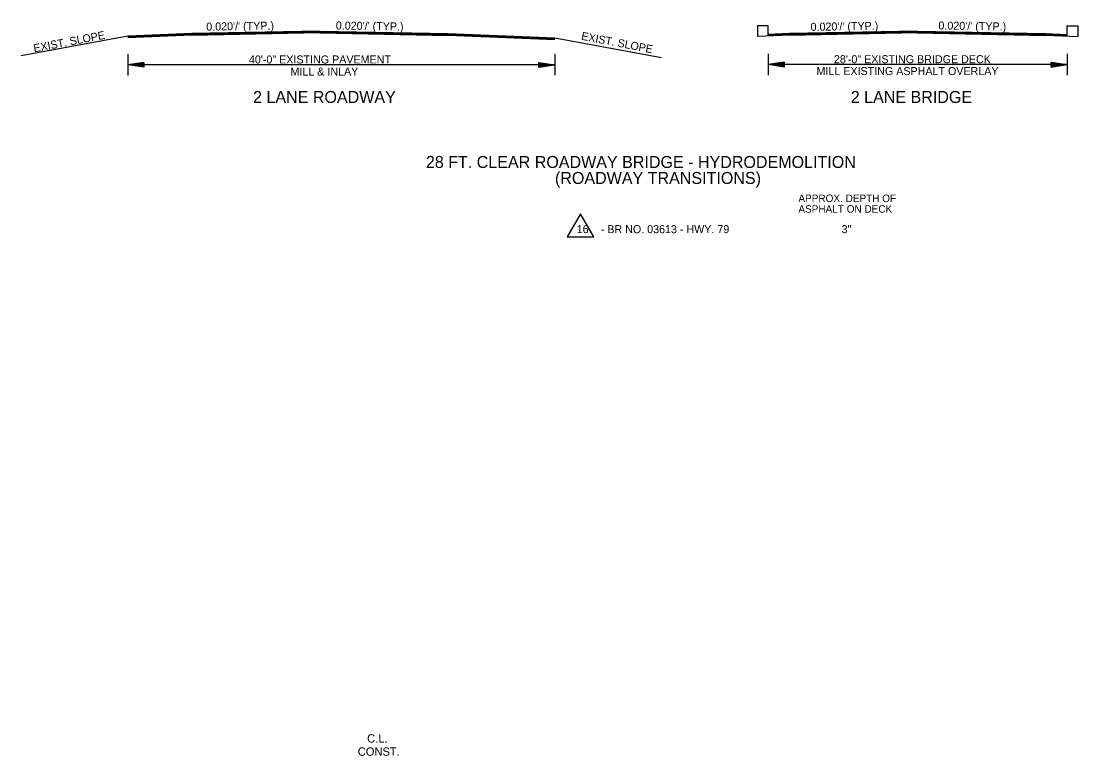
# Model space of a CAD drawing. Extents: x 549600 to 1930787, y -1955432 to 596640.
# Drawn here: x 551022 to 552012, y -1953335 to -1952647 of the extents above; entities that cross this region are included whole.
import ezdxf

# ---------------------------------------------------------------- set-up
doc = ezdxf.new("R2010")
doc.units = 0
for name, color, linetype in [('R_Border', 7, 'Continuous'), ('R_Border Notes', 7, 'Continuous'), ('S_AREA_CALC', 7, 'Continuous')]:
    doc.layers.add(name, color=color, linetype=linetype)

msp = doc.modelspace()

# ---------------------------------------------------------------- linework, layer by layer
at = {"layer": 'R_Border'}
for p, q in [((551711.85, -1952651.18), (551711.85, -1952661.29)), ((551722.02, -1952651.18), (551711.85, -1952651.18)), ((551722.02, -1952660.59), (551722.02, -1952651.18)), ((552002.02, -1952660.59), (552002.02, -1952651.18)), ((552002.02, -1952651.18), (552012.18, -1952651.18)), ((552012.18, -1952651.18), (552012.18, -1952661.29)), ((551533.72, -1952848.95), (551558.52, -1952848.95))]:
    msp.add_line(p, q, dxfattribs=at)
msp.add_lwpolyline([(551558.52, -1952848.95), (551546.12, -1952827.47), (551533.72, -1952848.95)], dxfattribs=at)
at = {"layer": 'S_AREA_CALC'}
for p, q in [((551122.02, -1952660.99), (551021.95, -1952679.36)), ((551182.02, -1952658.59), (551122.02, -1952660.99)), ((551182.02, -1952658.89), (551122.02, -1952661.29)), ((551182.02, -1952659.19), (551122.02, -1952661.59)), ((551182.02, -1952659.49), (551122.02, -1952661.89)), ((551182.02, -1952659.79), (551122.02, -1952662.19)), ((551182.02, -1952660.09), (551122.02, -1952662.49)), ((551302.02, -1952656.19), (551182.02, -1952658.59)), ((551302.02, -1952656.49), (551182.02, -1952658.89)), ((551302.02, -1952656.79), (551182.02, -1952659.19)), ((551302.02, -1952657.09), (551182.02, -1952659.49)), ((551302.02, -1952657.39), (551182.02, -1952659.79)), ((551302.02, -1952657.69), (551182.02, -1952660.09)), ((551302.02, -1952657.86), (551182.02, -1952660.26)), ((551302.02, -1952656.19), (551422.02, -1952658.59)), ((551302.02, -1952656.49), (551422.02, -1952658.89)), ((551302.02, -1952656.79), (551422.02, -1952659.19)), ((551302.02, -1952657.09), (551422.02, -1952659.49)), ((551302.02, -1952657.39), (551422.02, -1952659.79)), ((551302.02, -1952657.69), (551422.02, -1952660.09)), ((551302.02, -1952657.86), (551422.02, -1952660.26)), ((551422.02, -1952658.59), (551522.02, -1952662.59)), ((551422.02, -1952658.89), (551522.02, -1952662.89)), ((551422.02, -1952659.19), (551522.02, -1952663.19)), ((551422.02, -1952659.49), (551522.02, -1952663.49)), ((551422.02, -1952659.79), (551522.02, -1952663.79)), ((551422.02, -1952660.09), (551522.02, -1952664.09)), ((551522.02, -1952662.59), (551622.09, -1952680.96)), ((551742.02, -1952660.09), (551711.85, -1952661.29)), ((551742.02, -1952658.59), (551722.02, -1952659.39)), ((551742.02, -1952658.89), (551722.02, -1952659.69)), ((551742.02, -1952659.19), (551722.02, -1952659.99)), ((551742.02, -1952659.49), (551722.02, -1952660.29)), ((551742.02, -1952659.79), (551722.02, -1952660.59)), ((551862.02, -1952656.19), (551742.02, -1952658.59)), ((551862.02, -1952656.49), (551742.02, -1952658.89)), ((551862.02, -1952656.79), (551742.02, -1952659.19)), ((551862.02, -1952657.09), (551742.02, -1952659.49)), ((551862.02, -1952657.39), (551742.02, -1952659.79)), ((551862.02, -1952657.69), (551742.02, -1952660.09)), ((551862.02, -1952657.86), (551742.02, -1952660.26)), ((551862.02, -1952656.19), (551982.02, -1952658.59)), ((551862.02, -1952656.49), (551982.02, -1952658.89)), ((551862.02, -1952656.79), (551982.02, -1952659.19)), ((551862.02, -1952657.09), (551982.02, -1952659.49)), ((551862.02, -1952657.39), (551982.02, -1952659.79)), ((551862.02, -1952657.69), (551982.02, -1952660.09)), ((551862.02, -1952657.86), (551982.02, -1952660.26)), ((551982.02, -1952658.59), (552002.02, -1952659.39)), ((551982.02, -1952658.89), (552002.02, -1952659.69)), ((551982.02, -1952659.19), (552002.02, -1952659.99)), ((551982.02, -1952659.49), (552002.02, -1952660.29)), ((551982.02, -1952659.79), (552002.02, -1952660.59)), ((551982.02, -1952660.09), (552012.18, -1952661.29)), ((551122.02, -1952677.84), (551122.02, -1952697.84)), ((551522.02, -1952677.59), (551522.02, -1952697.59)), ((551722.02, -1952677.59), (551722.02, -1952697.59)), ((552002.02, -1952677.35), (552002.02, -1952697.35)), ((551137.02, -1952685.59), (551122.02, -1952687.84)), ((551137.02, -1952690.09), (551122.02, -1952687.84)), ((551522.02, -1952687.84), (551122.02, -1952687.84)), ((551137.02, -1952685.97), (551124.52, -1952687.84)), ((551137.02, -1952689.72), (551124.52, -1952687.84)), ((551137.02, -1952686.35), (551127.1, -1952687.84)), ((551137.02, -1952689.34), (551127.1, -1952687.84)), ((551137.02, -1952686.73), (551129.6, -1952687.84)), ((551137.02, -1952688.96), (551129.6, -1952687.84)), ((551137.02, -1952687.12), (551132.14, -1952687.84)), ((551137.02, -1952688.58), (551132.14, -1952687.84)), ((551137.02, -1952687.49), (551134.65, -1952687.84)), ((551137.02, -1952688.2), (551134.65, -1952687.84)), ((551137.02, -1952685.59), (551137.02, -1952690.09)), ((551507.02, -1952685.59), (551522.02, -1952687.84)), ((551507.02, -1952690.09), (551507.02, -1952685.59)), ((551507.02, -1952685.97), (551519.51, -1952687.84)), ((551507.02, -1952686.35), (551516.93, -1952687.84)), ((551507.02, -1952686.73), (551514.44, -1952687.84)), ((551507.02, -1952687.11), (551511.89, -1952687.84)), ((551507.02, -1952687.49), (551509.39, -1952687.84)), ((551507.02, -1952690.09), (551522.02, -1952687.84)), ((551507.02, -1952688.57), (551511.89, -1952687.84)), ((551507.02, -1952689.34), (551516.93, -1952687.84)), ((551507.02, -1952689.72), (551519.51, -1952687.84)), ((551507.02, -1952688.96), (551514.44, -1952687.84)), ((551507.02, -1952688.2), (551509.39, -1952687.84)), ((551737.02, -1952685.34), (551722.02, -1952687.59)), ((551737.02, -1952689.84), (551722.02, -1952687.59)), ((552002.02, -1952687.59), (551722.02, -1952687.59)), ((551737.02, -1952685.72), (551724.52, -1952687.59)), ((551737.02, -1952689.47), (551724.52, -1952687.59)), ((551737.02, -1952686.1), (551727.1, -1952687.59)), ((551737.02, -1952689.09), (551727.1, -1952687.59)), ((551737.02, -1952686.48), (551729.6, -1952687.59)), ((551737.02, -1952688.71), (551729.6, -1952687.59)), ((551737.02, -1952686.87), (551732.14, -1952687.59)), ((551737.02, -1952688.33), (551732.14, -1952687.59)), ((551737.02, -1952687.24), (551734.65, -1952687.59)), ((551737.02, -1952687.95), (551734.65, -1952687.59)), ((551737.02, -1952685.34), (551737.02, -1952689.84)), ((551987.02, -1952685.34), (552002.02, -1952687.59)), ((551987.02, -1952689.84), (551987.02, -1952685.34)), ((551987.02, -1952685.72), (551999.51, -1952687.59)), ((551987.02, -1952686.1), (551996.93, -1952687.59)), ((551987.02, -1952686.48), (551994.44, -1952687.59)), ((551987.02, -1952686.86), (551991.89, -1952687.59)), ((551987.02, -1952687.24), (551989.39, -1952687.59)), ((551987.02, -1952689.84), (552002.02, -1952687.59)), ((551987.02, -1952688.32), (551991.89, -1952687.59)), ((551987.02, -1952689.09), (551996.93, -1952687.59)), ((551987.02, -1952689.47), (551999.51, -1952687.59)), ((551987.02, -1952688.71), (551994.44, -1952687.59)), ((551987.02, -1952687.95), (551989.39, -1952687.59))]:
    msp.add_line(p, q, dxfattribs=at)

# ---------------------------------------------------------------- texts
at = {"layer": 'R_Border'}
for s, height, p in [('28 FT. CLEAR ROADWAY BRIDGE - HYDRODEMOLITION', 11.25, (551401.23, -1952784.46)), ('(ROADWAY TRANSITIONS)', 11.25, (551522.18, -1952799.46)), ('16', 7.5, (551542.55, -1952845.54)), ('- BR NO. 03613 - HWY. 79', 7.5, (551565.12, -1952845.54)), ('3"', 7.5, (551790.83, -1952845.54))]:
    msp.add_text(s, height=height, dxfattribs=at).set_placement(p)
at = {"layer": 'R_Border Notes'}
for s, p in [('APPROX. DEPTH OF', (551750.31, -1952816.36)), ('ASPHALT ON DECK', (551750.31, -1952826.36))]:
    msp.add_text(s, height=7, dxfattribs=at).set_placement(p)
at = {"layer": 'S_AREA_CALC'}
for s, rotation, p in [("0.020'/' (TYP.)", 0.97192, (551195.49, -1952655.78)), ("0.020'/' (TYP.)", 359.02808, (551316.79, -1952654.61)), ("0.020'/' (TYP.)", 0.97192, (551761.76, -1952655.98)), ("0.020'/' (TYP.)", 359.02808, (551881.5, -1952654.61)), ('EXIST. SLOPE', 10.88286, (551034.23, -1952676.15)), ('EXIST. SLOPE', 349.11714, (551546.4, -1952664.18))]:
    msp.add_text(s, height=7.5, rotation=rotation, dxfattribs=at).set_placement(p)
for s, height, p in [('40\'-0" EXISTING PAVEMENT', 7.5, (551235.39, -1952686.52)), ('28\'-0" EXISTING BRIDGE DECK', 7.5, (551783.57, -1952686.27)), ('MILL & INLAY', 7.5, (551274.34, -1952697.8)), ('MILL EXISTING ASPHALT OVERLAY', 7.5, (551767.29, -1952697.4)), ('2 LANE ROADWAY', 11.25, (551239.29, -1952723.56)), ('2 LANE BRIDGE', 11.25, (551799.39, -1952723.56)), ('C.L.', 7.8, (551346.17, -1953322.9)), ('CONST.', 7.8, (551337.39, -1953335.26))]:
    msp.add_text(s, height=height, dxfattribs=at).set_placement(p)

doc.saveas('drawing.dxf')
